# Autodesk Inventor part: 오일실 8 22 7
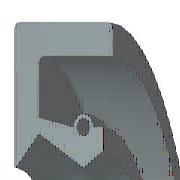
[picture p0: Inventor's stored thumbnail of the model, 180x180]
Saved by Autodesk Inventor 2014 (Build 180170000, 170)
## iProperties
IsCustomPart: 1
Created: 2012-02
Part Number: 오일실 8 22 7
Material: 고무
Description: 오일-실
Document SubType Name: Modeling
Standard: KS B 2804
Designer: mduedu
Standards Organization: KS
Language: ko-KR
Size Designation: D - 8 22 7
Categories: <MemberInstance><Categories><Category DisplayName="샤프트 부품" InternalName="7f7aeb1f-a693-4053-b835-cee3144e0d98" Mnemonic="SHFT"><Category DisplayName="실링" Intern
Density: 0.93 g/cm^3
Appearance: Rubber - Black - Version 1.1
Mass: 1.28441 g
Surface Area: 18.2787 cm^2
Volume: 1.38108 cm^3
Author: mduedu
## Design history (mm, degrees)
revolve "본체" stored, may be unused: angle "d17" = 90 deg
revolve "스프링1" stored, may be unused: angle "d18" = 90 deg
body "Solid1"
sketch "스케치1"
  geometry: L1 (0, 11)-(7, 11); L2 (7, 9.25)-(1.75, 9.25); L3 (1.75, 5.75)-(4.9, 4); L4 (4.9, 4)-(0, 4); L5 (0, 0)-(9.586, 0) reference; L6 (4.9, 4)-(6.3, 4.875); L7 (0, 18)-(0, -3) reference; L8 (-1.941, 0)-(11.507, 0) reference; L9 (4.2, 6.1)-(1.75, 6.59); L10 (1.75, 6.59)-(1.75, 9.25); L11 (0, 11)-(0, 4.088); L12 (4.9, 4)-(0, 4); L13 (1.75, 5.75)-(0.152, 4.028); L14 (7, 11)-(7, 9.25); L15 (5.6, 6.1)-(6.3, 6.1); L16 (6.3, 6.1)-(6.3, 4.875); C1 r 0.455 at (4.9, 6.1); A1 r 0.7 centre (4.9, 6.1) between (5.6, 6.1) and (4.2, 6.1); A2 r 0.088 centre (0.088, 4.088) between (0, 4.088) and (0.152, 4.028); 1 further point
  constraints: 28 end point, 5 horizontal alignment, 5 point on line, 4 point on circle, 4 vertical alignment, 3 centre point, 3 tangent, 2 collinear, 2 horizontal, 2 perpendicular, 1 coincident, 1 parallel
  dimensions: "d0" = 22 diameter of L1 L5 (= SD2); "d1" = 1.75 distance of L1.end L2.start (= SD); "d2" = 0.91 diameter of C1 (= SPDI); "d3" = 1.4 diameter of A1 (= SPDA); "d4" = 8 diameter of L3.end L5 (= NND); "d5" = 11.5 diameter of L3.start L5 (= TKDM); "d7" = 13.18 diameter of L9.end L5 (= TKDM + 0.24 x SWDT); "d8" = 1.75 distance between parallel lines of L11 L10 (= SD); "d9" = 4.9 distance from line of L11 C1.centre (= SPDST); "d10" = 12.2 diameter of C1.centre L5 (= HLDM); "d11" = 0.0875 radius of A2 (= 0.25 x LAB); "d12" = 6.3 distance between parallel lines of L11 L16 (= SDI); "d13" = 9.75 diameter of L6.end L5 (= ABDM); "d14" = 7 distance from line of L11 L1.end (= SWDT)
fillet "모깎기1" dims "d6" = 0.3 (= RR)
other parameters: "SD2" = 22 [user parameter; used in 1 equation term], "SWDT" = 7 [user parameter; used in 2 equation terms], "RR" = 0.3 [user parameter; used in 1 equation term], "SD" = 1.75 [user parameter; used in 2 equation terms], "NND" = 8 [user parameter; used in 1 equation term], "SPDA" = 1.4 [user parameter; used in 1 equation term], "SPDI" = 0.91 [user parameter; used in 1 equation term], "TKDM" = 11.5 [user parameter; used in 2 equation terms], "HLDM" = 12.2 [user parameter; used in 1 equation term], "ABDM" = 9.75 [user parameter; used in 1 equation term], "SDI" = 6.3 [user parameter; used in 1 equation term], "SPDST" = 4.9 [user parameter; used in 1 equation term], "LAB" = 0.35 [user parameter; used in 1 equation term], "d15" = 0, "d16" = 0, "d19" = 0
